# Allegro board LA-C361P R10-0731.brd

Outline 352.7 x 122.8 mm; copper layers: TOP, GND1, IN1, IN2, GND2, IN3, IN4, VCC, IN5, IN6, GND3, BOTTOM. Coordinates in mm from the lower left corner of the outline.

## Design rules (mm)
net group 15: nets N121029055 N121029061
net group CLK_27M: nets CLK_27M_IN CLK_27M_OUT
net group CLK_PCIE_CR: nets CLK_PCIE_CR CLK_PCIE_CR#
net group CLK_PCIE_SSD: nets CLK_PCIE_SSD CLK_PCIE_SSD#
net group CLK_PCIE_WLAN: nets CLK_PCIE_WLAN CLK_PCIE_WLAN#
net group CRITICAL: nets CLINK_CLK SUSCLK
net group CSS_1: nets CSSN_1 CSSP_1
net group DDI1_CPU_AUX: nets DDI1_CPU_AUXN DDI1_CPU_AUXP
net group DDI1DDI1_CPU_AUX_C: nets DDI1_CPU_AUXN_C DDI1_CPU_AUXP_C
net group DDI1DDI1_HTX_TBRX_0: nets DDI1_HTX_TBRX_N0 DDI1_HTX_TBRX_P0
net group DDI1DDI1_HTX_TBRX_0_C: nets DDI1_HTX_TBRX_N0_C DDI1_HTX_TBRX_P0_C
net group DDI1DDI1_HTX_TBRX_1: nets DDI1_HTX_TBRX_N1 DDI1_HTX_TBRX_P1
net group DDI1DDI1_HTX_TBRX_1_C: nets DDI1_HTX_TBRX_N1_C DDI1_HTX_TBRX_P1_C
net group DDI1DDI1_HTX_TBRX_2: nets DDI1_HTX_TBRX_N2 DDI1_HTX_TBRX_P2
net group DDI1DDI1_HTX_TBRX_2_C: nets DDI1_HTX_TBRX_N2_C DDI1_HTX_TBRX_P2_C
net group DDI1DDI1_HTX_TBRX_3: nets DDI1_HTX_TBRX_N3 DDI1_HTX_TBRX_P3
net group DDI1DDI1_HTX_TBRX_3_C: nets DDI1_HTX_TBRX_N3_C DDI1_HTX_TBRX_P3_C
net group DDI1DDI2_CPU_AUX: nets DDI2_CPU_AUXN DDI2_CPU_AUXP
net group DDI1DDI2_CPU_AUX_C: nets DDI2_CPU_AUXN_C DDI2_CPU_AUXP_C
net group DDI1DDI2_HTX_TBRX_0: nets DDI2_HTX_TBRX_N0 DDI2_HTX_TBRX_P0
net group DDI1DDI2_HTX_TBRX_0_C: nets DDI2_HTX_TBRX_N0_C DDI2_HTX_TBRX_P0_C
net group DDI1DDI2_HTX_TBRX_1: nets DDI2_HTX_TBRX_N1 DDI2_HTX_TBRX_P1
net group DDI1DDI2_HTX_TBRX_1_C: nets DDI2_HTX_TBRX_N1_C DDI2_HTX_TBRX_P1_C
net group DDI1DDI2_HTX_TBRX_2: nets DDI2_HTX_TBRX_N2 DDI2_HTX_TBRX_P2
net group DDI1DDI2_HTX_TBRX_2_C: nets DDI2_HTX_TBRX_N2_C DDI2_HTX_TBRX_P2_C
net group DDI1DDI2_HTX_TBRX_3: nets DDI2_HTX_TBRX_N3 DDI2_HTX_TBRX_P3
net group DDI1DDI2_HTX_TBRX_3_C: nets DDI2_HTX_TBRX_N3_C DDI2_HTX_TBRX_P3_C
net group DIFFPAIR0: nets DDC_CLK_HDMI DDC_DAT_HDMI
net group DIFFPAIR35: nets USB3TN1_D- USB3TP1_D+
net group DIFFPAIR36: nets USB3RN1_D- USB3RP1_D+
net group DIFFPAIR37: nets USB3TN1 USB3TP1
net group DIFFPAIR47: nets SD_LN1_M SD_LN1_P
net group DIFFPAIR48: nets SD_LN0_M SD_LN0_P
net group DIFFPAIR49: nets SD_RCLK_M SD_RCLK_P
net group DIFFPAIR51: nets USB3RN1_RE USB3RP1_RE
net group DIFFPAIR57: nets DOCK_TNY_SMB_CLK DOCK_TNY_SMB_DAT
net group DIFFPAIR59: nets TBTA_I2C_C_N TBTA_I2C_C_P
net group DIFFPAIR60: nets TBTA_USB2_D_N_C TBTA_USB2_D_P_C
net group DIFFPAIR61: nets TBT_USB3_TX0_N TBT_USB3_TX0_P
net group DIFFPAIR62: nets TBT_USB3_TX1_N TBT_USB3_TX1_P
net group EDP_AUXP_C: nets EDP_AUXN_C EDP_AUXP_C
net group EDP_TX2_R: nets EDP_TXN2_R EDP_TXP2_R
net group EDP_TX3_R: nets EDP_TXN3_R EDP_TXP3_R
net group PCIE_PRX_CARDTX_2: nets PCIE_PRX_CARDTX_N2 PCIE_PRX_CARDTX_P2
net group PCIE_PRX_CARDTX_2_C: nets PCIE_PRX_CARDTX_N2_C PCIE_PRX_CARDTX_P2_C
net group PCIE_PRX_SSDTX_10: nets PCIE_PRX_SSDTX_N10 PCIE_PRX_SSDTX_P10
net group PCIE_PRX_SSDTX_11: nets PCIE_PRX_SSDTX_N11 PCIE_PRX_SSDTX_P11
net group PCIE_PRX_SSDTX_12: nets PCIE_PRX_SSDTX_N12 PCIE_PRX_SSDTX_P12
net group PCIE_PRX_TBTX_15: nets PCIE_PRX_TBTX_N15 PCIE_PRX_TBTX_P15
net group PCIE_PRX_TBTX_16: nets PCIE_PRX_TBTX_N16 PCIE_PRX_TBTX_P16
net group PCIE_PRX_WLANTX_1: nets PCIE_PRX_WLANTX_N1 PCIE_PRX_WLANTX_P1
net group PCIE_PTX_CARDRX_2: nets PCIE_PTX_CARDRX_N2 PCIE_PTX_CARDRX_P2
net group PCIE_PTX_CARDRX_2_C: nets PCIE_PTX_CARDRX_N2_C PCIE_PTX_CARDRX_P2_C
net group PCIE_PTX_SSDRX_10: nets PCIE_PTX_SSDRX_N10 PCIE_PTX_SSDRX_P10
net group PCIE_PTX_SSDRX_10_C: nets PCIE_PTX_SSDRX_N10_C PCIE_PTX_SSDRX_P10_C
net group PCIE_PTX_SSDRX_11: nets PCIE_PTX_SSDRX_N11 PCIE_PTX_SSDRX_P11
net group PCIE_PTX_SSDRX_11_C: nets PCIE_PTX_SSDRX_N11_C PCIE_PTX_SSDRX_P11_C
net group PCIE_PTX_SSDRX_12: nets PCIE_PTX_SSDRX_N12 PCIE_PTX_SSDRX_P12
net group PCIE_PTX_SSDRX_12_C: nets PCIE_PTX_SSDRX_N12_C PCIE_PTX_SSDRX_P12_C
net group PCIE_PTX_TBRX_15: nets PCIE_PTX_TBRX_N15 PCIE_PTX_TBRX_P15
net group PCIE_PTX_TBRX_16: nets PCIE_PTX_TBRX_N16 PCIE_PTX_TBRX_P16
net group PCIE_PTX_WLANRX_1: nets PCIE_PTX_WLANRX_N1 PCIE_PTX_WLANRX_P1
net group PCIE_PTX_WLANRX_RE_1: nets PCIE_PTX_WLANRX_RE_N1 PCIE_PTX_WLANRX_RE_P1
net group REF-AGND: nets TBTA_CC1 TBTA_CC2
net group SATA_PRX_DTX_1B: nets SATA_PRX_DTX_N1B SATA_PRX_DTX_P1B
net group SATA_PRX_DTX_1B_RC: nets SATA_PRX_DTX_N1B_RC SATA_PRX_DTX_P1B_RC
net group SATA_PRX_SSDTX_0A: nets SATA_PRX_SSDTX_N0A SATA_PRX_SSDTX_P0A
net group SATA_PTX_DRX_1B: nets SATA_PTX_DRX_N1B SATA_PTX_DRX_P1B
net group SATA_PTX_DRX_1B_RC: nets SATA_PTX_DRX_N1B_RC SATA_PTX_DRX_P1B_RC
net group SATA_PTX_SSDRX_0A: nets SATA_PTX_SSDRX_N0A SATA_PTX_SSDRX_P0A
net group SATA_PTX_SSDRX_0A_C: nets SATA_PTX_SSDRX_N0A_C SATA_PTX_SSDRX_P0A_C
net group SD_RCLK_R: nets SD_RCLK_M_R SD_RCLK_P_R
net group SPI-CLK: nets PCH_SPI_CLK PCH_SPI_CLK_R
net group THERMTRIP: nets H_THERMTRIP# H_THERMTRIP#_R
net group USBP2_D: nets USBP2_D+ USBP2_D-
net group USBP2_R_D: nets USBP2_R_D+ USBP2_R_D-
net group 12: nets H_PECI UART2_RXD UART2_TXD
net group ASY: nets H_CPUPWRGD H_PROCHOT# H_PROCHOT#_R PCH_RSMRST#
net group DDI1: nets DDI1_DDPB_CTRLCLK DDI1_DDPB_CTRLDAT DDI1_PCH_HPD
net group DDI2: nets DDI2_DDPC_CTRLCLK DDI2_DDPC_CTRLDAT DDI2_PCH_HPD
net group DDR_CLK: nets M_CLK_DDR0 M_CLK_DDR1 M_CLK_DDR2 M_CLK_DDR3 M_CLK_DDR#0 M_CLK_DDR#1 M_CLK_DDR#2 M_CLK_DDR#3
net group DDR_DQS: nets DDR_A_DQS0 DDR_A_DQS1 DDR_A_DQS2 DDR_A_DQS3 DDR_A_DQS4 DDR_A_DQS5 DDR_A_DQS6 DDR_A_DQS7 DDR_A_DQS#0 DDR_A_DQS#1 DDR_A_DQS#2 DDR_A_DQS#3 DDR_A_DQS#4 DDR_A_DQS#5 DDR_A_DQS#6 DDR_A_DQS#7 DDR_B_DQS0 DDR_B_DQS1 DDR_B_DQS2 DDR_B_DQS3 DDR_B_DQS4 DDR_B_DQS5 DDR_B_DQS6 DDR_B_DQS7 DDR_B_DQS#0 DDR_B_DQS#1 DDR_B_DQS#2 DDR_B_DQS#3 DDR_B_DQS#4 DDR_B_DQS#5 DDR_B_DQS#6 DDR_B_DQS#7
net group DDRA_ADD: nets DDR_A_ACT# DDR_A_ALERT# DDR_A_BG0 DDR_A_BG1 DDR_A_BS0 DDR_A_BS1 DDR_A_CAS# DDR_A_MA0 DDR_A_MA1 DDR_A_MA2 DDR_A_MA3 DDR_A_MA4 DDR_A_MA5 DDR_A_MA6 DDR_A_MA7 DDR_A_MA8 DDR_A_MA9 DDR_A_MA10 DDR_A_MA11 DDR_A_MA12 DDR_A_MA13 DDR_A_PAR DDR_A_RAS# DDR_A_WE#
net group DDRA_CTRL: nets DDR_CKE0_DIMMA DDR_CKE1_DIMMA DDR_CS0_DIMMA# DDR_CS1_DIMMA# M_ODT0 M_ODT1
net group DDRA_D0: nets DDR_A_D0 DDR_A_D1 DDR_A_D2 DDR_A_D3 DDR_A_D4 DDR_A_D5 DDR_A_D6 DDR_A_D7
net group DDRA_D1: nets DDR_A_D8 DDR_A_D9 DDR_A_D10 DDR_A_D11 DDR_A_D12 DDR_A_D13 DDR_A_D14 DDR_A_D15
net group DDRA_D2: nets DDR_A_D16 DDR_A_D17 DDR_A_D18 DDR_A_D19 DDR_A_D20 DDR_A_D21 DDR_A_D22 DDR_A_D23
net group DDRA_D3: nets DDR_A_D24 DDR_A_D25 DDR_A_D26 DDR_A_D27 DDR_A_D28 DDR_A_D29 DDR_A_D30 DDR_A_D31
net group DDRA_D4: nets DDR_A_D32 DDR_A_D33 DDR_A_D34 DDR_A_D35 DDR_A_D36 DDR_A_D37 DDR_A_D38 DDR_A_D39
net group DDRA_D5: nets DDR_A_D40 DDR_A_D41 DDR_A_D42 DDR_A_D43 DDR_A_D44 DDR_A_D45 DDR_A_D46 DDR_A_D47
net group DDRA_D6: nets DDR_A_D48 DDR_A_D49 DDR_A_D50 DDR_A_D51 DDR_A_D52 DDR_A_D53 DDR_A_D54 DDR_A_D55
net group DDRA_D7: nets DDR_A_D56 DDR_A_D57 DDR_A_D58 DDR_A_D59 DDR_A_D60 DDR_A_D61 DDR_A_D62 DDR_A_D63
net group DDRB_ADD: nets DDR_B_ACT# DDR_B_ALERT# DDR_B_BG0 DDR_B_BG1 DDR_B_BS0 DDR_B_BS1 DDR_B_CAS# DDR_B_MA0 DDR_B_MA1 DDR_B_MA2 DDR_B_MA3 DDR_B_MA4 DDR_B_MA5 DDR_B_MA6 DDR_B_MA7 DDR_B_MA8 DDR_B_MA9 DDR_B_MA10 DDR_B_MA11 DDR_B_MA12 DDR_B_MA13 DDR_B_PAR DDR_B_RAS# DDR_B_WE#
net group DDRB_CTRL: nets DDR_CKE2_DIMMB DDR_CKE3_DIMMB DDR_CS2_DIMMB# DDR_CS3_DIMMB# M_ODT2 M_ODT3
net group DDRB_D0: nets DDR_B_D0 DDR_B_D1 DDR_B_D2 DDR_B_D3 DDR_B_D4 DDR_B_D5 DDR_B_D6 DDR_B_D7
net group DDRB_D1: nets DDR_B_D8 DDR_B_D9 DDR_B_D10 DDR_B_D11 DDR_B_D12 DDR_B_D13 DDR_B_D14 DDR_B_D15
net group DDRB_D2: nets DDR_B_D16 DDR_B_D17 DDR_B_D18 DDR_B_D19 DDR_B_D20 DDR_B_D21 DDR_B_D22 DDR_B_D23
net group DDRB_D3: nets DDR_B_D24 DDR_B_D25 DDR_B_D26 DDR_B_D27 DDR_B_D28 DDR_B_D29 DDR_B_D30 DDR_B_D31
net group DDRB_D4: nets DDR_B_D32 DDR_B_D33 DDR_B_D34 DDR_B_D35 DDR_B_D36 DDR_B_D37 DDR_B_D38 DDR_B_D39
net group DDRB_D5: nets DDR_B_D40 DDR_B_D41 DDR_B_D42 DDR_B_D43 DDR_B_D44 DDR_B_D45 DDR_B_D46 DDR_B_D47
net group DDRB_D6: nets DDR_B_D48 DDR_B_D49 DDR_B_D50 DDR_B_D51 DDR_B_D52 DDR_B_D53 DDR_B_D54 DDR_B_D55
net group DDRB_D7: nets DDR_B_D56 DDR_B_D57 DDR_B_D58 DDR_B_D59 DDR_B_D60 DDR_B_D61 DDR_B_D62 DDR_B_D63
net group DIFFPAIR38: nets USB3RP1
net group DMI: nets DMI_CRX_PTX_N0 DMI_CRX_PTX_N1 DMI_CRX_PTX_N2 DMI_CRX_PTX_N3 DMI_CRX_PTX_P0 DMI_CRX_PTX_P1 DMI_CRX_PTX_P2 DMI_CRX_PTX_P3 DMI_CTX_PRX_N0 DMI_CTX_PRX_N1 DMI_CTX_PRX_N2 DMI_CTX_PRX_N3 DMI_CTX_PRX_P0 DMI_CTX_PRX_P1 DMI_CTX_PRX_P2 DMI_CTX_PRX_P3
net group EDP: nets EDP_AUXN EDP_AUXN_R EDP_AUXP EDP_AUXP_R EDP_COMP EDP_HPD_S EDP_TXN0 EDP_TXN0_C EDP_TXN0_R EDP_TXN1 EDP_TXN1_C EDP_TXN1_R EDP_TXN2 EDP_TXN2_C EDP_TXN3 EDP_TXN3_C EDP_TXP0 EDP_TXP0_C EDP_TXP0_R EDP_TXP1 EDP_TXP1_C EDP_TXP1_R EDP_TXP2 EDP_TXP2_C EDP_TXP3 EDP_TXP3_C
net group HDA: nets HDA_RST# HDA_SDIN0 HDA_SDOUT HDA_SDOUT_AUDIO HDA_SYNC HDA_SYNC_AUDIO
net group HDA-CLK: nets HDA_BITCLK_AUDIO
net group HDMI: nets TMDS_L_TX0N TMDS_L_TX0P TMDS_L_TX1N TMDS_L_TX1P TMDS_L_TX2N TMDS_L_TX2P TMDS_L_TXCN TMDS_L_TXCP TMDS_TX0N TMDS_TX0P TMDS_TX1N TMDS_TX1P TMDS_TX2N TMDS_TX2P TMDS_TXCN TMDS_TXCP
net group LPC: nets LPC_AD0 LPC_AD1 LPC_AD2 LPC_AD3 LPC_FRAME#
net group PCIE-UT1: nets PCIE_PRX_TBTX_N15_C PCIE_PRX_TBTX_N16_C PCIE_PRX_TBTX_P15_C PCIE_PRX_TBTX_P16_C PCIE_PTX_TBRX_N15_C PCIE_PTX_TBRX_N16_C PCIE_PTX_TBRX_P15_C PCIE_PTX_TBRX_P16_C
net group PECI: nets PCH_PCIE_WAKE# PCH_PECI PCIE_WAKE#
net group PEG: nets PEG_GTX_C_HRX_N0 PEG_GTX_C_HRX_N1 PEG_GTX_C_HRX_N2 PEG_GTX_C_HRX_N3 PEG_GTX_C_HRX_N4 PEG_GTX_C_HRX_N5 PEG_GTX_C_HRX_N6 PEG_GTX_C_HRX_N7 PEG_GTX_C_HRX_N8 PEG_GTX_C_HRX_N9 PEG_GTX_C_HRX_N10 PEG_GTX_C_HRX_N11 PEG_GTX_C_HRX_N12 PEG_GTX_C_HRX_N13 PEG_GTX_C_HRX_N14 PEG_GTX_C_HRX_N15 PEG_GTX_C_HRX_P0 PEG_GTX_C_HRX_P1 PEG_GTX_C_HRX_P2 PEG_GTX_C_HRX_P3 PEG_GTX_C_HRX_P4 PEG_GTX_C_HRX_P5 PEG_GTX_C_HRX_P6 PEG_GTX_C_HRX_P7 PEG_GTX_C_HRX_P8 PEG_GTX_C_HRX_P9 PEG_GTX_C_HRX_P10 PEG_GTX_C_HRX_P11 PEG_GTX_C_HRX_P12 PEG_GTX_C_HRX_P13 PEG_GTX_C_HRX_P14 PEG_GTX_C_HRX_P15 PEG_GTX_HRX_N0 PEG_GTX_HRX_N1 PEG_GTX_HRX_N2 PEG_GTX_HRX_N3 PEG_GTX_HRX_N4 PEG_GTX_HRX_N5 PEG_GTX_HRX_N6 PEG_GTX_HRX_N7 PEG_GTX_HRX_N8 PEG_GTX_HRX_N9 PEG_GTX_HRX_N10 PEG_GTX_HRX_N11 PEG_GTX_HRX_N12 PEG_GTX_HRX_N13 PEG_GTX_HRX_N14 PEG_GTX_HRX_N15 PEG_GTX_HRX_P0 PEG_GTX_HRX_P1 PEG_GTX_HRX_P2 PEG_GTX_HRX_P3 PEG_GTX_HRX_P4 PEG_GTX_HRX_P5 PEG_GTX_HRX_P6 PEG_GTX_HRX_P7 PEG_GTX_HRX_P8 PEG_GTX_HRX_P9 PEG_GTX_HRX_P10 PEG_GTX_HRX_P11 PEG_GTX_HRX_P12 PEG_GTX_HRX_P13 PEG_GTX_HRX_P14 PEG_GTX_HRX_P15 PEG_HTX_C_GRX_N0 PEG_HTX_C_GRX_N1 PEG_HTX_C_GRX_N2 PEG_HTX_C_GRX_N3 PEG_HTX_C_GRX_N4 PEG_HTX_C_GRX_N5 PEG_HTX_C_GRX_N6 PEG_HTX_C_GRX_N7 PEG_HTX_C_GRX_N8 PEG_HTX_C_GRX_N9 PEG_HTX_C_GRX_N10 PEG_HTX_C_GRX_N11 PEG_HTX_C_GRX_N12 PEG_HTX_C_GRX_N13 PEG_HTX_C_GRX_N14 PEG_HTX_C_GRX_N15 PEG_HTX_C_GRX_P0 PEG_HTX_C_GRX_P1 PEG_HTX_C_GRX_P2 PEG_HTX_C_GRX_P3 PEG_HTX_C_GRX_P4 PEG_HTX_C_GRX_P5 PEG_HTX_C_GRX_P6 PEG_HTX_C_GRX_P7 PEG_HTX_C_GRX_P8 PEG_HTX_C_GRX_P9 PEG_HTX_C_GRX_P10 PEG_HTX_C_GRX_P11 PEG_HTX_C_GRX_P12 PEG_HTX_C_GRX_P13 PEG_HTX_C_GRX_P14 PEG_HTX_C_GRX_P15 PEG_HTX_GRX_N0 PEG_HTX_GRX_N1 PEG_HTX_GRX_N2 PEG_HTX_GRX_N3 PEG_HTX_GRX_N4 PEG_HTX_GRX_N5 PEG_HTX_GRX_N6 PEG_HTX_GRX_N7 PEG_HTX_GRX_N8 PEG_HTX_GRX_N9 PEG_HTX_GRX_N10 PEG_HTX_GRX_N11 PEG_HTX_GRX_N12 PEG_HTX_GRX_N13 PEG_HTX_GRX_N14 PEG_HTX_GRX_N15 PEG_HTX_GRX_P0 PEG_HTX_GRX_P1 PEG_HTX_GRX_P2 PEG_HTX_GRX_P3 PEG_HTX_GRX_P4 PEG_HTX_GRX_P5 PEG_HTX_GRX_P6 PEG_HTX_GRX_P7 PEG_HTX_GRX_P8 PEG_HTX_GRX_P9 PEG_HTX_GRX_P10 PEG_HTX_GRX_P11 PEG_HTX_GRX_P12 PEG_HTX_GRX_P13 PEG_HTX_GRX_P14 PEG_HTX_GRX_P15
net group PLATFORM CLK: nets CLK_PCIE_TBT CLK_PCIE_TBT# CLK_PEG_VGA CLK_PEG_VGA# CPU_24MHZ_N CPU_24MHZ_P PCH_CPU_BCLK_N PCH_CPU_BCLK_P PCH_CPU_PCIBCLK_N PCH_CPU_PCIBCLK_P PCH_XDP_CLK_N PCH_XDP_CLK_P
net group PLATFORM CLOCK-SE: nets CLK_PCI_MEC N120139517 SRCCLKREQ1# SRCCLKREQ2# SRCCLKREQ8# SRCCLKREQ9# SRCCLKREQ10# SRCCLKREQ11# SRCCLKREQ12# SRCCLKREQ13# SRCCLKREQ14# SRCCLKREQ15# XTAL24_IN XTAL24_OUT
net group PWR: nets +3V_PS8723 +3VALWP +3VLP +5VALWP +5VS_HDD +CLK_PLLVDD +EDPVDD +FB_VREF +FBA_PLL_AVDD +FBA_VREFC_H +FBA_VREFC_L +FBA_VREFD_H +FBA_VREFD_L +FBB_VREFC_H +FBB_VREFC_L +FBB_VREFD_H +FBB_VREFD_L +INV_PWR_SRC +PLLVDD +RTCBATT +V_DDR_REF +V_DDR_REFA_R +V_DDR_REFB_R +VDISPLAY_VCC +VGA_B+
net group RTC: nets PCH_RTCRST# PCH_RTCX1 PCH_RTCX2 PCH_SRTCRST#
net group SD: nets SD_CD# SD_CLK SD_CLK_R SD_CMD SD_CMD_R SD_D2 SD_D2_R SD_D3 SD_D3_R SD_REG2
net group SMB: nets BC_CLK_ECE1117 BC_DAT_ECE1117 CHARGER_SCL CHARGER_SDA CHARGER_SMBCLK CHARGER_SMBDAT CLK_SMB DAT_SMB EC_SMB_CK2_PX EC_SMB_DA2_PX I2C0_SCK_DSP I2C0_SDA_DSP PBAT_SMBCLK PBAT_SMBDAT PCH_SMBCLK PCH_SMBDATA SMBCLK SMBDATA SML1_SMBCLK SML1_SMBDAT UPD_GPU_SMBCLK UPD_GPU_SMBDAT UPD_SMBCLK UPD_SMBDAT USBC_MCP23017_SMBCLK USBC_MCP23017_SMBDAT
net group SPI: nets PCH_SPI_CS1# PCH_SPI_CS2# PCH_SPI_CS# PCH_SPI_HOLD# PCH_SPI_HOLD#_R PCH_SPI_SI PCH_SPI_SI_R PCH_SPI_SO PCH_SPI_SO_R PCH_SPI_WP# PCH_SPI_WP#_R
net group SVID: nets VR_SVID_ALERT# VR_SVID_CLK VR_SVID_DATA
net group TBT: nets TBT_LSRX TBT_LSTX TBT_ML0_N TBT_ML0_P TBT_ML1_N TBT_ML1_P TBT_ML2_N TBT_ML2_P TBT_ML3_N TBT_ML3_P TBT_USB2_D+ TBT_USB2_D- TBT_USB3_TX0_N_C TBT_USB3_TX0_P_C TBTA_AUX_N TBTA_AUX_N_C TBTA_AUX_P TBTA_AUX_P_C TBTA_I2C_D_N TBTA_I2C_D_P TBTA_SBU1 TBTA_SBU2 TBTA_USB2_D_N_R TBTA_USB2_D_P_R
net group TBT_RX/TX: nets TBT_USB3_RX0_N TBT_USB3_RX0_P TBT_USB3_RX1_N TBT_USB3_RX1_P TBT_USB3_TX1_N_C TBT_USB3_TX1_P_C
net group THERMAL DIODE: nets REM_DIODE1_N REM_DIODE1_P REM_DIODE2_N REM_DIODE2_P REM_DIODE3_N REM_DIODE3_P REM_DIODE4_N REM_DIODE4_P
net group USB2.0: nets USB20_N1 USB20_N2 USB20_N4 USB20_N4_R USB20_N9 USB20_N9_R USB20_N12 USB20_N12_R USB20_P1 USB20_P2 USB20_P4 USB20_P4_R USB20_P9_R USB20_P12 USB20_P12_R
net group USB3.0: nets USB3RN1 USB3RN1_C USB3RN2 USB3RN2_D- USB3RP1_C USB3RP2 USB3RP2_D+ USB3T_N1 USB3T_N2 USB3T_P1 USB3T_P2 USB3TN1_RE USB3TN2 USB3TN2_D- USB3TP1_RE USB3TP2 USB3TP2_D+ USBP1_D+ USBP1_D- USBP1_R_D+ USBP1_R_D-
net group USB20_N9: nets USB20_P9
net group VRAM_CLK: nets CLKA0 CLKA0# CLKA1 CLKA1# CLKB0 CLKB0# CLKB1 CLKB1#
net group VRAMA_ADD: nets FBA_CMD0 FBA_CMD1 FBA_CMD2 FBA_CMD3 FBA_CMD4 FBA_CMD5 FBA_CMD6 FBA_CMD7 FBA_CMD8 FBA_CMD9 FBA_CMD10 FBA_CMD11 FBA_CMD12 FBA_CMD13 FBA_CMD14 FBA_CMD15 FBA_CMD16 FBA_CMD17 FBA_CMD18 FBA_CMD19 FBA_CMD20 FBA_CMD21 FBA_CMD22 FBA_CMD23 FBA_CMD24 FBA_CMD25 FBA_CMD26 FBA_CMD27 FBA_CMD28 FBA_CMD29 FBA_CMD30 FBA_CMD31
net group VRAMA_D0: nets FBA_D0 FBA_D1 FBA_D2 FBA_D3 FBA_D4 FBA_D5 FBA_D6 FBA_D7 FBA_DBI0 FBA_EDC0
net group VRAMA_D1: nets FBA_D8 FBA_D9 FBA_D10 FBA_D11 FBA_D12 FBA_D13 FBA_D14 FBA_D15 FBA_DBI1 FBA_EDC1
net group VRAMA_D2: nets FBA_D16 FBA_D17 FBA_D18 FBA_D19 FBA_D20 FBA_D21 FBA_D22 FBA_D23 FBA_DBI2 FBA_EDC2
net group VRAMA_D3: nets FBA_D24 FBA_D25 FBA_D26 FBA_D27 FBA_D28 FBA_D29 FBA_D30 FBA_D31 FBA_DBI3 FBA_EDC3
net group VRAMA_D4: nets FBA_D32 FBA_D33 FBA_D34 FBA_D35 FBA_D36 FBA_D37 FBA_D38 FBA_D39 FBA_DBI4 FBA_EDC4
net group VRAMA_D5: nets FBA_D40 FBA_D41 FBA_D42 FBA_D43 FBA_D44 FBA_D45 FBA_D46 FBA_D47 FBA_DBI5 FBA_EDC5
net group VRAMA_D6: nets FBA_D48 FBA_D49 FBA_D50 FBA_D51 FBA_D52 FBA_D53 FBA_D54 FBA_D55 FBA_DBI6 FBA_EDC6
net group VRAMA_D7: nets FBA_D56 FBA_D57 FBA_D58 FBA_D59 FBA_D60 FBA_D61 FBA_D62 FBA_D63 FBA_DBI7 FBA_EDC7
net group VRAMA_WCK: nets FBA_WCK01 FBA_WCK01# FBA_WCK23 FBA_WCK23# FBA_WCK45 FBA_WCK45# FBA_WCK67 FBA_WCK67#
net group VRAMB_ADD: nets FBB_CMD0 FBB_CMD1 FBB_CMD2 FBB_CMD3 FBB_CMD4 FBB_CMD5 FBB_CMD6 FBB_CMD7 FBB_CMD8 FBB_CMD9 FBB_CMD10 FBB_CMD11 FBB_CMD12 FBB_CMD13 FBB_CMD14 FBB_CMD15 FBB_CMD16 FBB_CMD17 FBB_CMD18 FBB_CMD19 FBB_CMD20 FBB_CMD21 FBB_CMD22 FBB_CMD23 FBB_CMD24 FBB_CMD25 FBB_CMD26 FBB_CMD27 FBB_CMD28 FBB_CMD29 FBB_CMD30 FBB_CMD31
net group VRAMB_D0: nets FBB_D0 FBB_D1 FBB_D2 FBB_D3 FBB_D4 FBB_D5 FBB_D6 FBB_D7 FBB_DBI0 FBB_EDC0
net group VRAMB_D1: nets FBB_D8 FBB_D9 FBB_D10 FBB_D11 FBB_D12 FBB_D13 FBB_D14 FBB_D15 FBB_DBI1 FBB_EDC1
net group VRAMB_D2: nets FBB_D16 FBB_D17 FBB_D18 FBB_D19 FBB_D20 FBB_D21 FBB_D22 FBB_D23 FBB_DBI2 FBB_EDC2
net group VRAMB_D3: nets FBB_D24 FBB_D25 FBB_D26 FBB_D27 FBB_D28 FBB_D29 FBB_D30 FBB_D31 FBB_DBI3 FBB_EDC3
net group VRAMB_D4: nets FBB_D32 FBB_D33 FBB_D34 FBB_D35 FBB_D36 FBB_D37 FBB_D38 FBB_D39 FBB_DBI4 FBB_EDC4
net group VRAMB_D5: nets FBB_D40 FBB_D41 FBB_D42 FBB_D43 FBB_D44 FBB_D45 FBB_D46 FBB_D47 FBB_DBI5 FBB_EDC5
net group VRAMB_D6: nets FBB_D48 FBB_D49 FBB_D50 FBB_D51 FBB_D52 FBB_D53 FBB_D54 FBB_D55 FBB_DBI6 FBB_EDC6
net group VRAMB_D7: nets FBB_D56 FBB_D57 FBB_D58 FBB_D59 FBB_D60 FBB_D61 FBB_D62 FBB_D63 FBB_DBI7 FBB_EDC7
net group VRAMB_WCK: nets FBB_WCK01 FBB_WCK01# FBB_WCK23 FBB_WCK23# FBB_WCK45 FBB_WCK45# FBB_WCK67 FBB_WCK67#
nets with their own width: min track width 0.203; nets VCC1V8A_TBTA_LDO
nets with their own width: min track width 0.254; nets GPU_VDD_SENSE GPU_VSS_SENSE VCC_3V3_PCIE VCC_3V3_USB2
nets with their own width: min track width 0.305; nets N121070696
nets with their own width: min track width 0.508; nets +0.6VS +0.6VSP +0.95VSP +1.2V_DDR +1.2V_MEN_P +1.2V_PWROK +1.2V_VCCPLL_OC +1.05VSDGPU +1.05VSP +1.35V_RUN_B+ +1.35V_VSNS +1.35VSDGPU +1V_MPHY +1V_PCH +1V_PCH_AZPLL +1V_PCH_PRIM +1V_VCCDSW +1VALW +1VSP +2.5V_MEM +2.5VS_G9141 +3.3V_ALW_DEG +3.3V_GFX_AON +3.3V_GFX_RUN +3V_PCH +3V_PCH_AZIO +3V_PCH_DSW +3V_PCH_SPI +3V_ROM +3V_TBT +3V_TBT_PWR +3VA_TBT +3VA_TBT_LC +3VALW +3VALW_5085 +3VALW_23017 +3VS_CAM +3VS_CR +3VS_FFS +3VS_TP +3VS_TPM +3VS_TPM_VSB +3VS_TS +3VS_WLAN +5V_CHGUSB_1 +5V_CHGUSB_2 +5VALW +5VS +AC_IN +DC_IN +DC_IN_SS +FBA_DLL_AVDD +GPU_CORE +ODR_PWR +PEX_PLLVDD +PWR_SRC_AC +RTC_CELL_VBAT +RTCVCC +SD_VDD2 +SDC_IN +V_DDR_REFA +V_DDR_REFB +VBUS_1 +VBUS_DC_SS +VCC0V9_PCIE +VCC0V9_USB +VCC_CORE +VCCGT +VCCIO +VCCSA +VCCST +VCCSTG +VCHGR +VLDOIN_1.2V +VR_CAP B+ B++ GND TBTA_VBUS_L VCC3V3_FLASH VCC5V0_SYS
nets with their own width: min track width 1.524; nets +3VS +VSBP
nets with their own width: min track width 2.54; nets +3.3VDX_SSD

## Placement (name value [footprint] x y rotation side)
ADP100  ACES_50290-00701-001  [ACES_50290-00701-001_7P-T]  14.85 73.71 0 bottom
BAT100  ACES_50290-01201-P01  [ACES_50290-01201-P01_12P-T]  28.35 14.64 180 bottom
CD1  1U_0402_6.3V6K  [C_0402]  147.77 27.56 90 top
CD2  1U_0402_6.3V6K  [C_0402]  136.12 28.53 270 top
CD3  1U_0402_6.3V6K  [C_0402]  174.29 28.98 0 top
CD4  1U_0402_6.3V6K  [C_0402]  174.29 28.1 0 top
CD5  10U_0603_6.3V6M  [C_0603]  149.54 27.25 90 top
CD6  10U_0603_6.3V6M  [C_0603]  141.55 18.46 0 top
CD7  10U_0603_6.3V6M  [C_0603]  157.44 63.19 0 top
CD8  10U_0603_6.3V6M  [C_0603]  138.62 28.65 270 top
CD9  10U_0603_6.3V6M  [C_0603]  173.98 27.02 0 top
CD10  10U_0603_6.3V6M  [C_0603]  173.98 25.81 0 top
CD11  220U_D7_2VM_R6M  [C_EEFSS0D221R]  133.73 50.57 0 top
CD12  1U_0402_6.3V6K  [C_0402]  173.8 17.8 90 top
CD13  10U_0603_6.3V6M  [C_0603]  174.88 17.6 90 top
CD14  10U_0603_6.3V6M  [C_0603]  176.15 17.47 90 top
CD15  10U_0603_6.3V6M  [C_0603]  177.42 17.47 90 top
CD16  .1U_0402_16V7K  [C_0402]  171.82 26.88 180 top
CD17  2.2U_0402_6.3V6M  [C_0402]  171.93 25.8 180 top
CD18  .1U_0402_16V7K  [C_0402]  150.19 17.65 90 top
CD19  1U_0402_6.3V6K  [C_0402]  211.48 17.71 90 top
CD20  1U_0402_6.3V6K  [C_0402]  212.93 17.71 90 top
CD21  1U_0402_6.3V6K  [C_0402]  212.42 28.53 270 top
CD22  1U_0402_6.3V6K  [C_0402]  215.87 17.71 90 top
CD23  10U_0603_6.3V6M  [C_0603]  217.08 28.65 270 top
CD24  10U_0603_6.3V6M  [C_0603]  217.85 18.42 0 top
CD25  10U_0603_6.3V6M  [C_0603]  214.92 28.65 270 top
CD26  10U_0603_6.3V6M  [C_0603]  211.39 28.65 270 top
CD27  10U_0603_6.3V6M  [C_0603]  250.18 27.38 0 top
CD28  10U_0603_6.3V6M  [C_0603]  250.11 26.12 0 top
CD29  .1U_0402_16V7K  [C_0402]  226.5 17.65 90 top
CD30  1U_0402_6.3V6K  [C_0402]  251.46 29.51 0 top
CD31  1U_0402_6.3V6K  [C_0402]  250.84 28.48 0 top
CD32  1U_0402_6.3V6K  [C_0402]  250.33 17.46 90 top
CD33  220U_D7_2VM_R6M  [C_EEFSS0D221R]  147.2 50.57 0 top
CD34  .1U_0402_16V7K  [C_0402]  248.91 26.87 180 top
CD35  2.2U_0402_6.3V6M  [C_0402]  249.02 25.79 180 top
CD36  4.7U_0603_6.3V6K  [C_0603]  268.1 22.04 270 top
CD37  0.22U_0402_10V6K  [C_0402]  257.1 20.2 0 bottom
CD38  .1U_0402_16V7K  [C_0402]  268.43 19.57 180 top
CD39  0.01U_0402_16V7K  [C_0402]  268.43 18.55 180 top
CD40  47P_0402_50V8J  [C_0402]  268.43 4.45 180 top
CD41  15P_0402_50V8J  [C_0402]  268.43 5.47 180 top
CD42  0.22U_0402_10V6K  [C_0402]  257.1 19.31 0 bottom
CD43  0.22U_0402_10V6K  [C_0402]  257.1 17.15 0 bottom
CD44  0.22U_0402_10V6K  [C_0402]  257.1 16.26 0 bottom
CD45  0.22U_0402_10V6K  [C_0402]  257.1 14.23 0 bottom
CD46  0.22U_0402_10V6K  [C_0402]  257.1 13.34 0 bottom
CD47  0.1U_0402_10V7K  [C_0402]  254.89 6.24 270 bottom
CD51  0.22U_0402_10V6K  [C_0402]  257.1 10.3 0 bottom
CD53  0.22U_0402_10V6K  [C_0402]  257.1 11.18 0 bottom
CD69  .1U_0402_16V7K  [C_0402]  133.29 18.73 270 top
CD70  10U_0603_6.3V6M  [C_0603]  145.94 17.28 90 top
CD71  10U_0603_6.3V6M  [C_0603]  148.65 17.28 90 top
CD72  10U_0603_6.3V6M  [C_0603]  140.78 28.65 270 top
CD73  10U_0603_6.3V6M  [C_0603]  135.09 28.65 270 top
CD74  1U_0402_6.3V6K  [C_0402]  139.57 17.81 90 top
CD75  1U_0402_6.3V6K  [C_0402]  138.15 17.81 90 top
CD76  1U_0402_6.3V6K  [C_0402]  136.63 17.81 90 top
CD77  1U_0402_6.3V6K  [C_0402]  135.18 17.81 90 top
CD78  1U_0402_6.3V6K  [C_0402]  143.56 28.53 270 top
CD79  1U_0402_6.3V6K  [C_0402]  142.16 28.53 270 top
CD80  1U_0402_6.3V6K  [C_0402]  224.07 27.56 90 top
CD81  1U_0402_6.3V6K  [C_0402]  219.86 28.53 270 top
CD82  1U_0402_6.3V6K  [C_0402]  218.46 28.53 270 top
CD83  1U_0402_6.3V6K  [C_0402]  214.45 17.71 90 top
CD84  10U_0603_6.3V6M  [C_0603]  229.6 19.58 180 top
CD85  10U_0603_6.3V6M  [C_0603]  225.84 27.25 90 top
CD86  10U_0603_6.3V6M  [C_0603]  224.95 17.28 90 top
CD87  10U_0603_6.3V6M  [C_0603]  222.24 17.28 90 top
CD88  10U_0603_6.3V6M  [C_0603]  253.95 17.47 90 top
CD89  10U_0603_6.3V6M  [C_0603]  252.68 17.47 90 top
CD90  10U_0603_6.3V6M  [C_0603]  251.41 17.47 90 top
CE8  27P_0402_50V8J  [C_0402]  150.22 9.47 90 top
CE11  0.1U_0402_25V6  [C_0402]  158.24 4.96 0 top
CE12  0.1U_0402_25V6  [C_0402]  149.8 5.66 180 top
CE13  0.1U_0402_25V6  [C_0402]  153.62 11.69 180 top
CE14  10U_0603_6.3V6M  [C_0603]  150.05 4.58 180 top
CE15  .1U_0402_16V7K  [C_0402]  349.51 116.73 270 top
CE16  10P_0402_25V8J  [C_0402]  348.04 116.73 270 top
CE17  0.1U_0402_25V6  [C_0402]  291.21 12.79 270 top
CE18  0.1U_0402_25V6  [C_0402]  306.38 14.11 0 top
CE19  1U_0402_6.3V6K  [C_0402]  306.38 13.22 0 top
CE20  0.1U_0402_25V6  [C_0402]  291.21 14.94 270 top
CE21  1U_0402_6.3V6K  [C_0402]  290.32 14.94 270 top
CE22  10U_0603_6.3V6M  [C_0603]  308.23 22.93 270 top
CE23  0.1U_0402_25V6  [C_0402]  304.55 23.3 90 top
CE24  0.1U_0402_25V6  [C_0402]  301.5 7.45 270 top
CE25  0.1U_0402_25V6  [C_0402]  306.38 16.14 0 top
CE26  0.1U_0402_25V6  [C_0402]  294.22 7.45 270 top
CE27  0.1U_0402_25V6  [C_0402]  299.09 23.3 90 top
CE28  0.1U_0402_25V6  [C_0402]  291.16 17.66 180 top
CE29  1U_0402_6.3V6K  [C_0402]  294.26 4.12 90 top
CE30  1U_0402_6.3V6K  [C_0402]  293.33 7.45 270 top
CE31  0.047U_0402_25V7K  [C_0402]  306.33 11.9 270 top
CE32  2200P_0402_25V7K  [C_0402]  303.79 6.54 90 top
CE33  2200P_0402_25V7K  [C_0402]  304.93 6.41 90 top
CE34  0.1U_0402_25V6  [C_0402]  291.16 22.11 180 top
CE35  2200P_0402_25V7K  [C_0402]  305.94 7.32 270 top
CE36  2200P_0402_25V7K  [C_0402]  312.37 9.41 180 top
CE37  1U_0402_6.3V6K  [C_0402]  285.75 14.94 270 top
CE38  1U_0402_6.3V6K  [C_0402]  288.93 14.03 90 top
CE39  47P_0402_50V8J  [C_0402]  294.01 23.3 90 top
CE40  4.7U_0603_6.3V6K  [C_0603]  302.64 7.31 270 top
CE41  0.1U_0402_25V6  [C_0402]  306.3 10.08 0 top
CE42  22P_0402_50V8J  [C_0402]  288.93 12.91 270 top
CE43  22P_0402_50V8J  [C_0402]  288.93 10.22 90 top
CE44  1U_0402_6.3V6K  [C_0402]  297.1 23.38 0 top
CE45  100P_0402_50V8J  [C_0402]  116.33 115.27 270 bottom
CE46  100P_0402_50V8J  [C_0402]  166.31 118.69 90 bottom
CE47  100P_0402_50V8J  [C_0402]  182.09 75.23 0 top
CE48  4.7P_0402_50V8C  [C_0402]  308.15 17.66 0 top
CE49  100P_0402_50V8J  [C_0402]  180.21 49.08 90 bottom
CE50  100P_0402_50V8J  [C_0402]  281.89 25.41 180 bottom
CE51  4700P_0402_25V7K  [C_0402]  298.71 7.45 270 top
CE52  0.1U_0402_25V6  [C_0402]  306.33 19.9 270 top
CE53  10U_0603_6.3V6M  [C_0603]  274.83 8.45 270 top
CE54  0.1U_0402_25V6  [C_0402]  278.56 8.39 0 top
CE55  0.1U_0402_25V6  [C_0402]  278.56 9.28 0 top
CE65  2200P_0402_25V7K  [C_0402]  223.19 11.06 0 top
CE66  0.01U_0402_16V7K  [C_0402]  100.33 34.81 90 top
CE67  0.01U_0402_16V7K  [C_0402]  322.84 38.31 270 top
CE68  100P_0402_50V8J  [C_0402]  27.1 52.33 0 top
CE69  100P_0402_50V8J  [C_0402]  158.33 72.08 0 top
CE70  1U_0402_6.3V6K  [C_0402]  292.36 7.45 270 top
CE71  1U_0402_6.3V6K  [C_0402]  289.82 4.12 90 top
CE72  100P_0402_50V8J  [C_0402]  241.17 115.91 270 bottom
CE73  4.7P_0402_50V8C  [C_0402]  154.38 9.03 180 bottom
CE74  4.7P_0402_50V8C  [C_0402]  154.37 10.82 270 bottom
CE75  0.1U_0402_25V6  [C_0402]  158.17 9.15 0 top
CE76  10U_0603_6.3V6M  [C_0603]  158.18 10.3 0 top
CE77  22P_0402_50V8J  [C_0402]  216.17 7.88 180 top
CE78  22P_0402_50V8J  [C_0402]  217.25 9.79 180 top
CE79  22P_0402_50V8J  [C_0402]  218.25 14.73 90 bottom
CE80  22P_0402_50V8J  [C_0402]  217.3 14.73 90 bottom
CE81  4.7P_0402_50V8C  [C_0402]  165.15 8.64 0 bottom
CE82  4.7P_0402_50V8C  [C_0402]  165.15 9.53 0 bottom
CF1  10U_0603_6.3V6M  [C_0603]  233.07 52.35 270 top
CF2  0.1U_0402_25V6  [C_0402]  231.03 57.59 90 top
CH3  0.1U_0402_25V6  [C_0402]  121.79 95.47 270 bottom
CH5  0.22U_0201_6.3V6M  [C_0201]  195.14 87.07 0 bottom
CH6  0.22U_0201_6.3V6M  [C_0201]  195.14 87.96 0 bottom
CH7  0.22U_0201_6.3V6M  [C_0201]  192.91 85.92 0 bottom
CH8  0.22U_0201_6.3V6M  [C_0201]  192.91 86.81 0 bottom
CH9  0.22U_0201_6.3V6M  [C_0201]  195.14 84.59 0 bottom
CH10  0.22U_0201_6.3V6M  [C_0201]  195.14 85.48 0 bottom
CH11  0.22U_0201_6.3V6M  [C_0201]  192.91 84.4 0 bottom
CH12  0.22U_0201_6.3V6M  [C_0201]  192.91 83.51 0 bottom
CH13  0.22U_0201_6.3V6M  [C_0201]  195.14 82.24 0 bottom
CH14  0.22U_0201_6.3V6M  [C_0201]  195.14 83.13 0 bottom
CH15  0.22U_0201_6.3V6M  [C_0201]  192.91 81.99 0 bottom
CH16  0.22U_0201_6.3V6M  [C_0201]  192.91 81.1 0 bottom
CH17  0.22U_0201_6.3V6M  [C_0201]  193.93 79.36 0 bottom
CH18  0.22U_0201_6.3V6M  [C_0201]  193.93 80.25 0 bottom
CH19  0.22U_0201_6.3V6M  [C_0201]  192.91 77.8 0 bottom
CH20  0.22U_0201_6.3V6M  [C_0201]  192.91 78.69 0 bottom
CH21  0.22U_0201_6.3V6M  [C_0201]  192.06 76.91 0 bottom
CH22  0.22U_0201_6.3V6M  [C_0201]  192.06 76.02 0 bottom
CH23  0.22U_0201_6.3V6M  [C_0201]  190.63 74.24 0 bottom
CH24  0.22U_0201_6.3V6M  [C_0201]  190.63 75.13 0 bottom
CH25  0.22U_0201_6.3V6M  [C_0201]  192.06 72.87 0 bottom
CH26  0.22U_0201_6.3V6M  [C_0201]  192.06 73.76 0 bottom
CH27  0.22U_0201_6.3V6M  [C_0201]  190.63 71.46 0 bottom
CH28  0.22U_0201_6.3V6M  [C_0201]  190.63 72.35 0 bottom
CH29  0.22U_0201_6.3V6M  [C_0201]  192.06 71.22 0 bottom
CH30  0.22U_0201_6.3V6M  [C_0201]  192.06 70.33 0 bottom
CH31  0.22U_0201_6.3V6M  [C_0201]  191.24 68.49 0 bottom
CH32  0.22U_0201_6.3V6M  [C_0201]  191.24 69.38 0 bottom
CH33  0.22U_0201_6.3V6M  [C_0201]  192.06 67.76 0 bottom
CH34  0.22U_0201_6.3V6M  [C_0201]  192.06 66.87 0 bottom
CH35  0.22U_0201_6.3V6M  [C_0201]  191.24 65.31 0 bottom
CH36  0.22U_0201_6.3V6M  [C_0201]  191.24 66.2 0 bottom
CH44  1U_0402_6.3V6K  [C_0402]  328.8 76.17 90 top
CH45  8.2P_0402_50V8D  [C_0402]  98.86 2.74 0 top
CH46  8.2P_0402_50V8D  [C_0402]  98.86 1.81 0 top
CH47  15P_0402_50V8J  [C_0402]  103.05 26.88 90 top
CH48  18P_0402_50V8J  [C_0402]  103.04 25.99 270 top
CH50  10P_0402_25V8J  [C_0402]  103.46 3.95 180 bottom
CH51  10P_0402_25V8J  [C_0402]  96.37 6.07 0 top
CH52  1U_0402_6.3V6K  [C_0402]  94.11 5.22 180 top
CH53  1U_0402_6.3V6K  [C_0402]  105.78 4.05 270 top
CH70  0.1U_0402_10V7K  [C_0402]  86.63 5.27 180 top
CH80  1U_0402_6.3V6K  [C_0402]  89.12 7.9 90 top
CH82  1U_0402_6.3V6K  [C_0402]  92.76 16.77 0 top
CH100  0.022U_0402_25V7K  [C_0402]  231.31 19.39 270 top
CH101  0.022U_0402_25V7K  [C_0402]  122 19.24 270 top
CH102  10U_0603_6.3V6M  [C_0603]  173.15 71.32 270 top
CH103  10U_0603_6.3V6M  [C_0603]  173.07 73.73 270 top
CH104  10U_0603_6.3V6M  [C_0603]  173.06 76.09 90 top
CH105  1U_0402_6.3V6K  [C_0402]  175.29 83.38 0 top
CH106  1U_0402_6.3V6K  [C_0402]  174.91 82.44 0 top
CH107  1U_0402_6.3V6K  [C_0402]  173.1 79.28 0 top
CH108  1U_0402_6.3V6K  [C_0402]  173.29 80.66 180 top
CH109  1U_0402_6.3V6K  [C_0402]  174.91 81.17 0 top
CH110  1U_0402_6.3V6K  [C_0402]  173 78.41 0 top
CH111  10U_0603_6.3V6M  [C_0603]  170.36 83.13 270 top
CH112  10U_0603_6.3V6M  [C_0603]  174.8 86.12 90 top
CH113  10U_0603_6.3V6M  [C_0603]  173.59 86.12 90 top
CH114  10U_0603_6.3V6M  [C_0603]  178.4 86.06 90 top
CH115  10U_0603_6.3V6M  [C_0603]  170.38 85.23 90 top
CH116  10U_0603_6.3V6M  [C_0603]  172.64 84.97 0 top
CH117  10U_0603_6.3V6M  [C_0603]  177.99 83.4 90 top
CH118  22U_0603_6.3V6M  [C_0603]  151.11 66.62 90 top
CH119  10U_0603_6.3V6M  [C_0603]  155.89 66.37 90 top
CH120  22U_0603_6.3V6M  [C_0603]  170.36 62.76 90 top
CH121  22U_0603_6.3V6M  [C_0603]  149.12 64.51 0 top
CH122  10U_0603_6.3V6M  [C_0603]  157.59 65.99 90 top
CH123  10U_0603_6.3V6M  [C_0603]  163.84 62.52 180 top
CH124  22U_0603_6.3V6M  [C_0603]  149.46 66.62 90 top
CH125  10U_0603_6.3V6M  [C_0603]  161.22 65.32 90 top
CH126  10U_0603_6.3V6M  [C_0603]  167.8 62.73 90 top
CH127  10U_0603_6.3V6M  [C_0603]  171.63 67.5 180 top
CH128  10U_0603_6.3V6M  [C_0603]  173.05 62.4 0 top
CH129  22U_0603_6.3V6M  [C_0603]  168.25 50.23 0 top
CH130  22U_0603_6.3V6M  [C_0603]  168.25 48.51 0 top
CH131  22U_0603_6.3V6M  [C_0603]  168.25 46.73 0 top
CH132  22U_0603_6.3V6M  [C_0603]  168.25 44.89 0 top
CH133  1U_0402_6.3V6K  [C_0402]  172.55 86.04 90 top
CH134  1U_0402_6.3V6K  [C_0402]  170.99 87.55 180 top
CH135  1U_0402_6.3V6K  [C_0402]  171 84.09 180 top
CH136  47U_0603_6.3V6M  [C_0603]  171.3 93.29 90 bottom
CH138  330U_B2_2.5VM_R9M  [C_B2]  173.7 90.9 270 bottom
CH173  0.1U_0402_10V7K  [C_0402]  88.23 7.9 90 top
CH174  0.1U_0402_25V6  [C_0402]  130.47 94.65 270 top
CH175  0.1U_0402_25V6  [C_0402]  122.68 95.46 270 bottom
CH176  1U_0402_6.3V6K  [C_0402]  85.59 6.57 90 top
CH177  22U_0603_6.3V6M  [C_0603]  102.3 17.12 270 bottom
CH178  22U_0603_6.3V6M  [C_0603]  102.3 20.04 270 bottom
CH179  1U_0402_6.3V6K  [C_0402]  101.84 21.15 0 bottom
CH180  1U_0402_6.3V6K  [C_0402]  76.98 27.19 180 top
CH181  22U_0603_6.3V6M  [C_0603]  77.34 29.07 90 top
CH182  22U_0603_6.3V6M  [C_0603]  79.12 29.07 90 top
CH183  1U_0402_6.3V6K  [C_0402]  86.5 18.36 180 top
CH184  22U_0603_6.3V6M  [C_0603]  83.06 32.18 90 top
CH186  0.1U_0402_10V7K  [C_0402]  91.44 6.41 90 top
CH187  1U_0402_6.3V6K  [C_0402]  99.23 3.7 0 top
CH188  1U_0402_6.3V6K  [C_0402]  93.71 14.36 0 top
CH189  0.1U_0402_10V7K  [C_0402]  97.65 9.98 0 top
CH190  0.1U_0402_10V7K  [C_0402]  79.52 14.49 180 top
CH191  0.1U_0402_10V7K  [C_0402]  79.2 10.93 180 top
CH192  0.1U_0402_10V7K  [C_0402]  77.09 4.34 270 top
CH196  15P_0402_50V8J  [C_0402]  89.16 6.89 180 top
CH197  0.1U_0402_10V7K  [C_0402]  121.37 53.18 180 top
CH198  15P_0402_50V8J  [C_0402]  108.28 4.07 0 bottom
CH199  15P_0402_50V8J  [C_0402]  109.21 4.96 0 bottom
CH200  0.1U_0402_10V7K  [C_0402]  92.67 6.64 0 top
CH201  22U_0603_6.3V6M  [C_0603]  105.45 12.58 0 top
CH202  22U_0603_6.3V6M  [C_0603]  102.02 11.06 0 top
CH203  0.1U_0402_10V7K  [C_0402]  91.44 10.66 90 top
CI1  0.1U_0402_25V6  [C_0402]  24.52 87.58 270 top
CI2  0.1U_0402_25V6  [C_0402]  332.66 61.6 0 bottom
CI3  0.1U_0402_10V7K  [C_0402]  323.33 34.3 0 bottom
CI4  0.01U_0402_16V7K  [C_0402]  315.93 29.73 180 bottom
CI5  0.1U_0402_10V7K  [C_0402]  321.18 27.75 90 bottom
CI6  0.1U_0402_10V7K  [C_0402]  320.3 27.75 90 bottom
CI7  0.1U_0402_10V7K  [C_0402]  319.41 27.75 90 bottom
CI8  0.1U_0402_10V7K  [C_0402]  318.52 27.75 90 bottom
CI9  0.1U_0402_10V7K  [C_0402]  21.9 104.02 0 bottom
CI10  0.1U_0402_10V7K  [C_0402]  21.9 104.91 0 bottom
CI11  47U_0805_6.3V6M  [C_0805]  21.97 107.7 90 top
CI12  10U_0603_6.3V6M  [C_0603]  20.19 108 90 top
CI13  0.1U_0402_25V6  [C_0402]  18.8 108.14 90 top
CI16  0.1U_0402_10V7K  [C_0402]  320.3 36.13 90 bottom
CI17  47U_0805_6.3V6M  [C_0805]  332.61 67.06 180 top
CI18  10U_0603_6.3V6M  [C_0603]  332.74 69.1 180 top
CI19  0.1U_0402_25V6  [C_0402]  332.94 70.49 180 top
CI20  0.1U_0402_10V7K  [C_0402]  321.18 36.13 90 bottom
CI21  0.1U_0402_10V7K  [C_0402]  26.16 86.67 90 top
CI22  0.1U_0402_10V7K  [C_0402]  322.07 53.53 90 top
CLRP1  SHORT PADS  [SHORTPADS]  106.81 2.42 270 bottom
CN1  22U_0603_6.3V6M  [C_0603]  325.46 85.16 180 bottom
CN2  .1U_0402_16V7K  [C_0402]  325.39 90.12 180 bottom
CN6  22U_0603_6.3V6M  [C_0603]  325.46 86.94 180 bottom
CN7  .1U_0402_16V7K  [C_0402]  325.39 91.13 180 bottom
CN8  .1U_0402_16V7K  [C_0402]  325.39 88.34 180 bottom
CN9  1000P_0402_50V7K  [C_0402]  325.39 89.23 180 bottom
CN20  0.1U_0402_10V7K  [C_0402]  330.96 80.65 90 bottom
CN21  0.1U_0402_10V7K  [C_0402]  332.11 80.65 90 bottom
CN22  2200P_0402_25V7K  [C_0402]  334.21 102.05 180 top
CR1  0.1U_0402_10V7K  [C_0402]  329.01 34.65 270 bottom
CR2  0.1U_0402_10V7K  [C_0402]  328.05 36.58 180 bottom
CR3  1U_0402_6.3V6K  [C_0402]  331.6 39.7 90 bottom
CR4  10U_0603_6.3V6M  [C_0603]  327.86 35.15 270 bottom
CR5  0.1U_0402_10V7K  [C_0402]  328.04 31.45 270 bottom
CR6  4.7U_0603_6.3V6K  [C_0603]  329.9 32.62 180 bottom
CR7  0.1U_0402_10V7K  [C_0402]  335.34 30.7 90 bottom
CR8  10P_0402_25V8J  [C_0402]  329.44 40.73 270 bottom
CR9  0.1U_0402_10V7K  [C_0402]  334.46 30.7 90 bottom
CR10  0.1U_0402_10V7K  [C_0402]  332.74 30.7 90 bottom
CR11  0.1U_0402_10V7K  [C_0402]  340.49 35.84 270 bottom
CR12  4.7U_0603_6.3V6K  [C_0603]  341.57 36.39 270 bottom
CR13  0.1U_0402_10V7K  [C_0402]  331.85 30.7 90 bottom
CR14  10U_0603_6.3V6M  [C_0603]  325.38 49.98 270 top
CR15  0.1U_0402_10V7K  [C_0402]  325.38 50.92 90 top
CR16  1U_0402_6.3V6K  [C_0402]  336.81 39.51 90 bottom
CR17  4.7U_0603_6.3V6K  [C_0603]  347.22 45.86 0 bottom
CR18  0.1U_0402_10V7K  [C_0402]  347.65 47.06 0 bottom
CS12  1000P_0402_50V7K  [C_0402]  236.73 12.51 90 bottom
CS13  .1U_0402_16V7K  [C_0402]  238.51 12.51 90 bottom
CS14  1U_0402_6.3V6K  [C_0402]  237.62 12.51 90 bottom
CS15  10U_0603_6.3V6M  [C_0603]  239.69 12.84 0 bottom
CS17  0.01U_0402_16V7K  [C_0402]  232.92 13.42 270 bottom
CS18  0.01U_0402_16V7K  [C_0402]  233.81 13.42 270 bottom
CS19  0.01U_0402_16V7K  [C_0402]  235.71 13.42 270 bottom
CS20  0.01U_0402_16V7K  [C_0402]  234.82 13.42 270 bottom
CT1  0.22U_0201_6.3V6M  [C_0201]  30.61 33.18 90 bottom
CT2  0.22U_0201_6.3V6M  [C_0201]  31.88 33.77 270 bottom
CT3  0.22U_0201_6.3V6M  [C_0201]  31.18 33.18 90 bottom
CT4  0.22U_0201_6.3V6M  [C_0201]  32.45 33.77 270 bottom
CT5  0.22U_0201_6.3V6M  [C_0201]  27.81 33.18 90 bottom
CT6  0.22U_0201_6.3V6M  [C_0201]  29.27 33.77 270 bottom
CT7  0.22U_0201_6.3V6M  [C_0201]  28.39 33.18 90 bottom
CT8  0.22U_0201_6.3V6M  [C_0201]  29.85 33.77 270 bottom
CT17  0.1U_0201_6.3V6K  [C_0201]  34.76 42.87 0 bottom
CT18  0.1U_0201_6.3V6K  [C_0201]  34.76 42.24 0 bottom
CT19  0.1U_0201_6.3V6K  [C_0201]  35.94 41.16 0 bottom
CT20  0.1U_0201_6.3V6K  [C_0201]  35.94 41.79 0 bottom
CT21  0.1U_0201_6.3V6K  [C_0201]  34.76 40.14 0 bottom
CT22  0.1U_0201_6.3V6K  [C_0201]  34.76 40.78 0 bottom
CT23  0.1U_0201_6.3V6K  [C_0201]  36.17 39.06 0 bottom
CT24  0.1U_0201_6.3V6K  [C_0201]  36.17 39.63 0 bottom
CT25  0.1U_0201_6.3V6K  [C_0201]  33.36 40.78 0 top
CT26  0.1U_0201_6.3V6K  [C_0201]  33.36 41.35 0 top
CT29  0.1U_0201_6.3V6K  [C_0201]  34.76 37.92 0 bottom
CT30  0.1U_0201_6.3V6K  [C_0201]  34.76 38.55 0 bottom
CT31  0.1U_0201_6.3V6K  [C_0201]  36.17 36.03 0 bottom
CT32  0.1U_0201_6.3V6K  [C_0201]  36.17 36.66 0 bottom
CT33  0.1U_0201_6.3V6K  [C_0201]  36.16 34.55 0 bottom
CT34  0.1U_0201_6.3V6K  [C_0201]  36.16 35.19 0 bottom
CT35  0.1U_0201_6.3V6K  [C_0201]  34.61 33.21 0 bottom
CT36  0.1U_0201_6.3V6K  [C_0201]  34.61 33.84 0 bottom
CT37  0.22U_0201_6.3V6M  [C_0201]  20.18 38.24 180 bottom
CT38  0.22U_0201_6.3V6M  [C_0201]  20.18 38.81 180 bottom
CT39  0.22U_0201_6.3V6M  [C_0201]  19.93 36.47 180 bottom
CT40  0.22U_0201_6.3V6M  [C_0201]  19.93 37.04 180 bottom
CT41  0.1U_0201_6.3V6K  [C_0201]  33.36 38.93 0 top
CT42  0.1U_0201_6.3V6K  [C_0201]  33.36 38.36 0 top
CT43  10P_0402_25V8J  [C_0402]  21.65 32.28 270 bottom
CT44  10P_0402_25V8J  [C_0402]  26.66 31.7 0 bottom
CT47  0.1U_0201_6.3V6K  [C_0201]  42.18 28.09 0 bottom
CT50  1U_0201_6.3V6M  [C_0201]  34.39 42.81 180 top
CT52  1U_0201_6.3V6M  [C_0201]  19.31 45.86 90 bottom
CT53  10U_0402_6.3V6M  [C_0402]  20.33 41.97 270 bottom
CT54  10U_0402_6.3V6M  [C_0402]  19.44 41.97 270 bottom
CT55  10U_0402_6.3V6M  [C_0402]  20.08 45.75 90 bottom
CT56  10U_0402_6.3V6M  [C_0402]  18.54 45.35 90 bottom
CT62  1U_0201_6.3V6M  [C_0201]  27.19 45.39 0 top
CT63  1U_0201_6.3V6M  [C_0201]  28.03 43.7 0 top
CT64  1U_0201_6.3V6M  [C_0201]  27.19 46 0 top
CT65  1U_0201_6.3V6M  [C_0201]  27.22 40.24 180 top
CT66  1U_0201_6.3V6M  [C_0201]  30.65 38.26 180 top
CT67  1U_0201_6.3V6M  [C_0201]  31.75 38.15 270 top
CT68  1U_0201_6.3V6M  [C_0201]  32.39 38.15 270 top
CT71  1U_0201_6.3V6M  [C_0201]  28.16 35.86 270 top
CT72  1U_0201_6.3V6M  [C_0201]  28.92 35.86 270 top
CT74  1U_0201_6.3V6M  [C_0201]  22.26 43.7 180 top
CT80  1U_0201_6.3V6M  [C_0201]  26 35.9 270 top
CT81  1U_0201_6.3V6M  [C_0201]  26.63 35.86 270 top
CT82  1U_0201_6.3V6M  [C_0201]  27.39 35.86 270 top
CT83  1U_0201_6.3V6M  [C_0201]  22.26 43.06 180 top
CT84  1U_0201_6.3V6M  [C_0201]  22.26 44.33 180 top
CT85  1U_0201_6.3V6M  [C_0201]  22.26 41.79 180 top
CT86  1U_0201_6.3V6M  [C_0201]  22.26 42.43 180 top
CT88  47U_0603_6.3V6M  [C_0603]  23.61 45.61 180 top
CT89  47U_0603_6.3V6M  [C_0603]  23.24 46.81 90 top
CT90  47U_0603_6.3V6M  [C_0603]  21.97 47.82 90 top
CT93  1U_0201_6.3V6M  [C_0201]  28.55 37.63 180 top
CT94  1U_0201_6.3V6M  [C_0201]  28.79 38.24 0 top
CT95  10U_0402_6.3V6M  [C_0402]  22.25 39.21 180 top
CT96  10U_0402_6.3V6M  [C_0402]  22.24 38.3 180 top
CT97  10U_0402_6.3V6M  [C_0402]  22.25 41 180 top
CT98  10U_0402_6.3V6M  [C_0402]  22.25 40.12 180 top
CT99  1U_0201_6.3V6M  [C_0201]  25.49 38.31 270 top
CT100  1U_0201_6.3V6M  [C_0201]  25.46 38.93 90 top
CT101  1U_0201_6.3V6M  [C_0201]  31.79 44.2 180 top
CT102  1U_0201_6.3V6M  [C_0201]  32.3 42.93 180 top
CT103  1U_0201_6.3V6M  [C_0201]  32.32 43.56 180 top
CT105  10U_0603_6.3V6M  [C_0603]  17.78 32.03 90 top
CT106  470P_0402_50V7K  [C_0402]  19.94 30.69 270 top
CT107  0.1U_0201_6.3V6K  [C_0201]  33.36 39.57 0 top
CT108  0.1U_0201_6.3V6K  [C_0201]  33.36 40.14 0 top
CT120  0.47U_0402_25V6K  [C_0402]  11.81 66.76 270 bottom
CT121  0.47U_0402_25V6K  [C_0402]  10.92 66.76 270 bottom
CT122  0.47U_0402_25V6K  [C_0402]  8 65.11 270 bottom
CT123  0.47U_0402_25V6K  [C_0402]  8.13 66.73 90 bottom
CT141  1U_0201_6.3V6M  [C_0201]  25.78 46.02 270 top
CT142  1U_0201_6.3V6M  [C_0201]  25.15 46.02 270 top
CT143  1U_0201_6.3V6M  [C_0201]  24.3 42.3 180 top
CT144  1U_0201_6.3V6M  [C_0201]  12.41 37.98 0 top
CT145  1U_0201_6.3V6M  [C_0201]  11.2 35.68 270 top
CT146  10U_0402_6.3V6M  [C_0402]  12.92 41.3 0 bottom
CT147  22U_0603_6.3V6M  [C_0603]  4.66 42.2 180 bottom
CT148  22U_0603_6.3V6M  [C_0603]  4.66 43.42 180 bottom
CT149  22U_0603_6.3V6M  [C_0603]  4.66 40.98 180 bottom
CT150  22U_0603_6.3V6M  [C_0603]  4.66 39.76 180 bottom
CT151  1U_0201_6.3V6M  [C_0201]  13.11 34.69 0 bottom
CT152  1U_0201_6.3V6M  [C_0201]  11.01 42.52 90 bottom
CT153  1U_0603_25V6  [C_0603]  3.23 29.99 0 bottom
CT155  4.7U_0603_25V6K  [C_0603]  8.14 40.23 0 top
CT157  1U_0603_25V6  [C_0603]  5.21 33.63 270 bottom
CT158  0.22U_0402_10V6K  [C_0402]  6.78 35.49 90 top
CT159  220P_0402_50V7K  [C_0402]  6.22 33.74 270 top
CT160  220P_0402_50V7K  [C_0402]  7.11 33.74 270 top
CT161  1U_0201_6.3V6M  [C_0201]  12.32 39.89 180 top
CT162  10U_0603_6.3V6M  [C_0603]  19.05 32.03 90 top
CT163  1U_0201_6.3V6M  [C_0201]  28.44 40.19 180 top
CT164  47U_0603_6.3V6M  [C_0603]  22.18 35.56 90 top
CT165  47U_0603_6.3V6M  [C_0603]  19.1 41.09 90 top
CV129  0.1U_0402_10V7K  [C_0402]  199.59 48.84 180 top
CV156  8.2P_0402_50V8D  [C_0402]  64.95 32.65 0 top
CV157  10U_0603_6.3V6M  [C_0603]  64.11 30.49 0 top
CV158  0.1U_0402_10V7K  [C_0402]  63.25 22.03 90 bottom
CV159  0.1U_0402_10V7K  [C_0402]  64.14 22.03 90 bottom
CV160  0.1U_0402_10V7K  [C_0402]  65.15 22.03 90 bottom
CV161  0.1U_0402_10V7K  [C_0402]  66.04 22.03 90 bottom
CV162  0.1U_0402_10V7K  [C_0402]  69.47 22.03 90 bottom
CV163  0.1U_0402_10V7K  [C_0402]  70.36 22.03 90 bottom
CV164  0.1U_0402_10V7K  [C_0402]  71.38 22.03 90 bottom
CV165  0.1U_0402_10V7K  [C_0402]  72.26 22.03 90 bottom
CV166  0.1U_0402_10V7K  [C_0402]  62.23 22.03 90 bottom
CV167  0.1U_0402_10V7K  [C_0402]  61.34 22.03 90 bottom
CV168  1U_0603_25V6  [C_0603]  47.31 21.73 0 bottom
CV169  0.1U_0402_25V6  [C_0402]  51.74 25.6 0 bottom
CV170  0.1U_0201_6.3V6K  [C_0201]  25.41 50.22 270 bottom
CV171  0.1U_0201_6.3V6K  [C_0201]  26 50.22 270 bottom
CV172  0.1U_0201_6.3V6K  [C_0201]  28.89 48.24 270 bottom
CV173  0.1U_0201_6.3V6K  [C_0201]  29.47 48.24 270 bottom
CV174  0.1U_0201_6.3V6K  [C_0201]  27.75 48.24 270 bottom
CV175  0.1U_0201_6.3V6K  [C_0201]  28.32 48.24 270 bottom
CV176  0.1U_0201_6.3V6K  [C_0201]  26.62 48 270 bottom
CV177  0.1U_0201_6.3V6K  [C_0201]  27.18 47.99 270 bottom
CV178  0.1U_0402_10V7K  [C_0402]  14.73 88.86 270 top
CV179  10U_0603_6.3V6M  [C_0603]  15.88 89.23 270 top
CV180  0.1U_0402_25V6  [C_0402]  14.94 88.91 180 bottom
CV181  0.1U_0402_25V6  [C_0402]  14.94 88.02 180 bottom
CV182  0.1U_0402_25V6  [C_0402]  14.94 87.13 180 bottom
CV183  .1U_0402_16V7K  [C_0402]  62.17 30.95 270 top
CV184  8.2P_0402_50V8D  [C_0402]  61.28 30.95 270 top
CV185  10U_0603_6.3V6M  [C_0603]  60.22 30.58 180 top
CV363  0.1U_0402_25V6  [C_0402]  201.87 59.9 270 bottom
CV531  0.22U_0201_6.3V6M  [C_0201]  197.54 71.64 180 top
CV532  0.22U_0201_6.3V6M  [C_0201]  197.54 70.76 180 top
CV533  0.22U_0201_6.3V6M  [C_0201]  199.44 70.5 180 top
CV534  0.22U_0201_6.3V6M  [C_0201]  199.44 69.61 180 top
CV535  0.22U_0201_6.3V6M  [C_0201]  199.44 71.9 180 top
CV536  0.22U_0201_6.3V6M  [C_0201]  199.44 72.79 180 top
CV537  0.22U_0201_6.3V6M  [C_0201]  197.54 73.04 180 top
CV538  0.22U_0201_6.3V6M  [C_0201]  197.54 73.93 180 top
CV539  0.22U_0201_6.3V6M  [C_0201]  199.44 74.18 180 top
CV540  0.22U_0201_6.3V6M  [C_0201]  199.44 75.07 180 top
CV541  0.22U_0201_6.3V6M  [C_0201]  197.54 75.58 180 top
CV542  0.22U_0201_6.3V6M  [C_0201]  197.54 76.47 180 top
CV543  0.22U_0201_6.3V6M  [C_0201]  199.44 76.47 180 top
CV544  0.22U_0201_6.3V6M  [C_0201]  199.44 77.36 180 top
CV545  0.22U_0201_6.3V6M  [C_0201]  197.54 78.76 180 top
CV546  0.22U_0201_6.3V6M  [C_0201]  197.54 77.87 180 top
CV547  0.22U_0201_6.3V6M  [C_0201]  199.44 78.76 180 top
CV548  0.22U_0201_6.3V6M  [C_0201]  199.44 79.65 180 top
CV550  0.22U_0201_6.3V6M  [C_0201]  197.54 80.15 180 top
CV551  0.22U_0201_6.3V6M  [C_0201]  197.54 81.04 180 top
CV552  0.22U_0201_6.3V6M  [C_0201]  197.54 84.09 180 top
CV557  0.22U_0201_6.3V6M  [C_0201]  197.54 84.98 180 top
CV558  0.22U_0201_6.3V6M  [C_0201]  197.54 83.33 180 top
CV559  0.22U_0201_6.3V6M  [C_0201]  197.54 82.44 180 top
CV560  0.22U_0201_6.3V6M  [C_0201]  199.31 81.8 180 top
CV561  0.22U_0201_6.3V6M  [C_0201]  199.31 80.92 180 top
CV562  0.22U_0201_6.3V6M  [C_0201]  197.54 85.74 180 top
CV563  0.22U_0201_6.3V6M  [C_0201]  197.54 86.63 180 top
CV564  0.22U_0201_6.3V6M  [C_0201]  197.54 87.52 180 top
CV565  0.22U_0201_6.3V6M  [C_0201]  197.54 88.41 180 top
CV566  0.22U_0201_6.3V6M  [C_0201]  197.56 89.3 180 top
CV567  0.22U_0201_6.3V6M  [C_0201]  197.56 90.19 180 top
CV570  0.1U_0402_10V7K  [C_0402]  207.2 71.95 90 top
CV571  0.1U_0402_10V7K  [C_0402]  206.62 69.33 0 top
CV572  10U_0603_6.3V6M  [C_0603]  206.25 63.83 0 top
CV573  47U_0805_6.3V6M  [C_0805]  206.22 65.35 0 top
CV574  22U_0603_6.3V6M  [C_0603]  210.15 67.95 180 top
CV575  10P_0402_25V8J  [C_0402]  222.94 57.92 0 bottom
CV576  10P_0402_25V8J  [C_0402]  222.07 57.92 180 bottom
CV580  1U_0402_6.3V6K  [C_0402]  206.57 77.07 0 top
CV581  1U_0402_6.3V6K  [C_0402]  206.57 76.18 0 top
CV582  4.7U_0603_6.3V6K  [C_0603]  207.18 79.59 270 top
CV583  10U_0603_6.3V6M  [C_0603]  200.09 61.35 180 top
CV584  10U_0603_6.3V6M  [C_0603]  200.09 62.62 180 top
CV585  22U_0603_6.3V6M  [C_0603]  198.46 64.27 180 top
CV586  22U_0603_6.3V6M  [C_0603]  198.46 66.05 180 top
CV587  22U_0603_6.3V6M  [C_0603]  219.08 69.83 0 top
CV588  10U_0603_6.3V6M  [C_0603]  208.11 84.73 90 top
CV589  22U_0603_6.3V6M  [C_0603]  219.84 72.53 0 top
CV590  22U_0603_6.3V6M  [C_0603]  212 84.68 270 top
CV591  1U_0402_6.3V6K  [C_0402]  219.65 83.93 0 top
CV592  1U_0402_6.3V6K  [C_0402]  215.81 85.11 180 top
CV593  0.1U_0402_25V6  [C_0402]  210.02 84.46 0 top
CV594  0.1U_0402_25V6  [C_0402]  224.64 91.94 0 top
CV595  1U_0402_6.3V6K  [C_0402]  206.52 81.74 0 top
CV596  1U_0402_6.3V6K  [C_0402]  206.52 80.85 0 top
CV597  4.7U_0603_6.3V6K  [C_0603]  206.29 83.64 0 top
CV598  10U_0603_6.3V6M  [C_0603]  202.25 90.77 90 top
CV599  10U_0603_6.3V6M  [C_0603]  203.47 90.78 90 top
CV600  22U_0603_6.3V6M  [C_0603]  200.36 67.93 0 top
CV601  22U_0603_6.3V6M  [C_0603]  200.36 66.18 0 top
CV602  22U_0603_6.3V6M  [C_0603]  224.35 93.04 0 top
CV603  10U_0603_6.3V6M  [C_0603]  218.03 88.79 90 top
CV604  22U_0603_6.3V6M  [C_0603]  218.15 74.3 180 top
CV605  22U_0603_6.3V6M  [C_0603]  218.31 85.89 0 top
CV606  1U_0402_6.3V6K  [C_0402]  215.48 89.4 90 top
CV607  1U_0402_6.3V6K  [C_0402]  219.98 78.37 180 top
CV608  0.1U_0402_25V6  [C_0402]  219.97 79.26 180 top
CV609  0.1U_0402_25V6  [C_0402]  220.62 75.07 0 top
CV610  0.1U_0402_10V7K  [C_0402]  205.46 85.21 90 top
CV611  1U_0402_6.3V6K  [C_0402]  206.6 85.78 90 top
CV612  4.7U_0603_6.3V6K  [C_0603]  196.72 91.26 0 top
CV613  1U_0402_6.3V6K  [C_0402]  203.7 89.86 0 top
CV614  0.1U_0402_10V7K  [C_0402]  204.9 70.84 180 top
CV615  4.7U_0603_6.3V6K  [C_0603]  204.64 69.78 180 top
CV616  4.7U_0603_6.3V6K  [C_0603]  204.64 68.58 180 top
CV617  4.7U_0603_6.3V6K  [C_0603]  214.73 69.1 180 top
CV619  1U_0402_6.3V6K  [C_0402]  217.11 68.35 270 top
CV621  0.1U_0402_10V7K  [C_0402]  218.06 68.35 270 top
CV622  0.1U_0402_10V7K  [C_0402]  216.22 68.35 270 top
CV623  0.1U_0402_10V7K  [C_0402]  215.71 69.24 90 top
CV636  0.1U_0402_10V7K  [C_0402]  220.57 76.58 90 top
CV637  0.1U_0402_10V7K  [C_0402]  227.29 95.91 90 top
CV638  0.01U_0402_16V7K  [C_0402]  221.64 85.3 90 top
CV639  0.1U_0402_10V7K  [C_0402]  226.36 96.82 270 top
CV650  820PF_0402_50V7K  [C_0402]  224.02 105.58 0 top
CV651  820PF_0402_50V7K  [C_0402]  217.49 112.22 180 top
CV652  10U_0603_6.3V6M  [C_0603]  222.45 104.23 0 top
CV653  1U_0402_6.3V6K  [C_0402]  212.97 112.33 0 top
CV654  1U_0402_6.3V6K  [C_0402]  215.66 112.33 180 top
CV655  0.1U_0402_10V7K  [C_0402]  220.14 112.09 0 top
CV656  0.1U_0402_10V7K  [C_0402]  222.42 107.17 270 top
CV657  0.1U_0402_10V7K  [C_0402]  215.57 99.45 0 top
CV658  0.1U_0402_10V7K  [C_0402]  221.92 112.09 0 top
CV659  10U_0603_6.3V6M  [C_0603]  223.9 112.09 0 top
CV660  1U_0402_6.3V6K  [C_0402]  221.5 105.04 180 top
CV661  1U_0402_6.3V6K  [C_0402]  223 99.45 0 top
CV662  0.1U_0402_10V7K  [C_0402]  214.71 99.45 180 top
CV663  0.1U_0402_10V7K  [C_0402]  221.22 99.45 0 top
CV675  820PF_0402_50V7K  [C_0402]  207.38 108.28 0 top
CV676  820PF_0402_50V7K  [C_0402]  202.25 112.92 270 top
CV677  10U_0603_6.3V6M  [C_0603]  192.2 110 270 top
CV678  1U_0402_6.3V6K  [C_0402]  196.81 112.92 0 top
CV679  1U_0402_6.3V6K  [C_0402]  204.2 112.02 0 top
CV680  0.1U_0402_10V7K  [C_0402]  203.38 106.69 0 top
CV681  0.1U_0402_10V7K  [C_0402]  196.81 112.03 0 top
CV682  0.1U_0402_10V7K  [C_0402]  191.87 111.95 90 top
CV683  0.1U_0402_10V7K  [C_0402]  204.8 103.39 180 top
CV684  10U_0603_6.3V6M  [C_0603]  201.88 98.92 0 top
CV685  1U_0402_6.3V6K  [C_0402]  196.43 98.25 0 bottom
CV686  1U_0402_6.3V6K  [C_0402]  205.09 99.46 180 top
CV687  0.1U_0402_10V7K  [C_0402]  197.63 99.13 270 top
CV688  0.1U_0402_10V7K  [C_0402]  196.7 99.15 270 top
CV700  820PF_0402_50V7K  [C_0402]  243.05 64.51 90 top
CV701  820PF_0402_50V7K  [C_0402]  248.29 64.93 270 top
CV702  10U_0603_6.3V6M  [C_0603]  247.34 77 90 top
CV703  1U_0402_6.3V6K  [C_0402]  245.66 70.85 270 top
CV704  1U_0402_6.3V6K  [C_0402]  235.64 66.77 90 top
CV705  0.1U_0402_10V7K  [C_0402]  238.99 67.08 270 top
CV706  0.1U_0402_10V7K  [C_0402]  234.45 76.86 90 top
CV707  0.1U_0402_10V7K  [C_0402]  236.74 67.18 90 top
CV708  0.1U_0402_10V7K  [C_0402]  235.03 74.61 90 top
CV709  10U_0603_6.3V6M  [C_0603]  235.51 61.45 180 bottom
CV710  1U_0402_6.3V6K  [C_0402]  247.14 68.8 270 top
CV711  1U_0402_6.3V6K  [C_0402]  246.15 73.72 270 top
CV712  0.1U_0402_10V7K  [C_0402]  247.15 69.68 90 top
CV713  0.1U_0402_10V7K  [C_0402]  247.15 75.08 90 top
CV725  820PF_0402_50V7K  [C_0402]  242.39 82.56 180 top
CV726  820PF_0402_50V7K  [C_0402]  247.52 86.84 0 top
CV727  10U_0603_6.3V6M  [C_0603]  235.88 85.35 270 top
CV728  1U_0402_6.3V6K  [C_0402]  234.32 96.1 270 top
CV729  1U_0402_6.3V6K  [C_0402]  241.66 91.26 90 top
CV730  0.1U_0402_10V7K  [C_0402]  236.92 89.4 180 top
CV731  0.1U_0402_10V7K  [C_0402]  242.96 85.3 90 top
CV732  0.1U_0402_10V7K  [C_0402]  238.61 87.17 90 top
CV733  0.1U_0402_10V7K  [C_0402]  244.04 98.09 0 top
CV734  10U_0603_6.3V6M  [C_0603]  245.66 82.62 270 top
CV735  1U_0402_6.3V6K  [C_0402]  247.21 95.82 90 top
CV736  1U_0402_6.3V6K  [C_0402]  243.36 82.56 0 top
CV737  0.1U_0402_10V7K  [C_0402]  234.27 92.85 90 top
CV738  0.1U_0402_10V7K  [C_0402]  234.26 88.18 270 top
CV773  0.1U_0402_10V7K  [C_0402]  208.51 70.76 270 top
CV776  820PF_0402_50V7K  [C_0402]  211.15 107.45 180 top
CV777  820PF_0402_50V7K  [C_0402]  193.82 106.66 0 top
CV778  820PF_0402_50V7K  [C_0402]  241.85 79.28 90 top
CV789  820PF_0402_50V7K  [C_0402]  243.6 99.59 90 top
CV790  1U_0402_6.3V6K  [C_0402]  230.57 98.08 180 top
CV791  22U_0603_6.3V6M  [C_0603]  228.66 95.31 90 top
CV792  0.1U_0402_10V7K  [C_0402]  220.43 64.93 180 top
CV793  0.1U_0402_10V7K  [C_0402]  221.62 64.65 90 top
CV794  0.1U_0402_10V7K  [C_0402]  205.35 72.53 0 top
CV795  1U_0402_6.3V6K  [C_0402]  222.9 59.39 270 top
CV796  1U_0402_6.3V6K  [C_0402]  204.78 67.51 0 top
